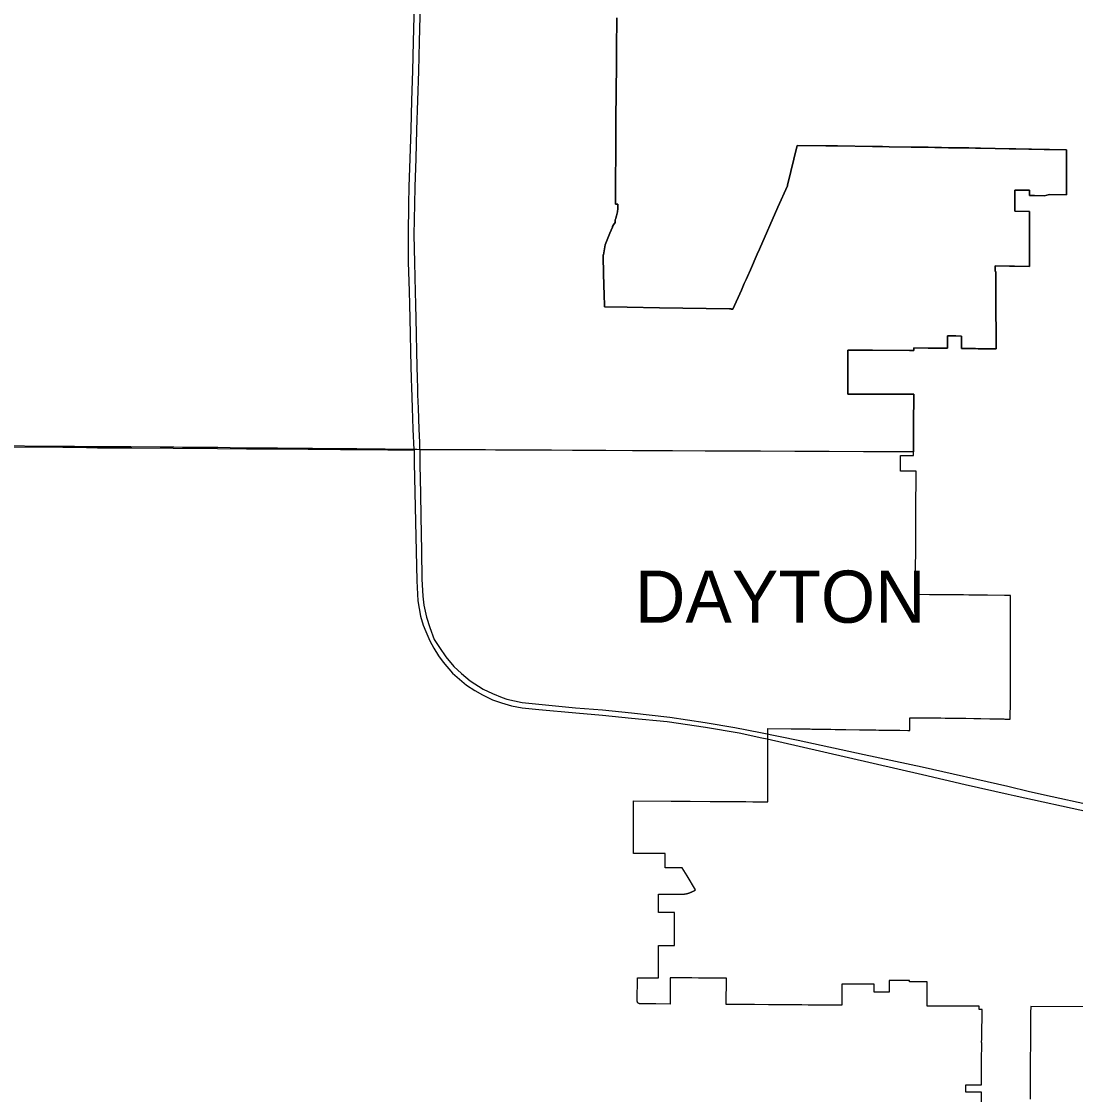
# Model space of a CAD drawing. Extents: x 0 to 34, y 0 to 22.
# Drawn here: x 4.8006 to 4.9631, y 15.001 to 15.1664 of the extents above; entities that cross this region are included whole.
import ezdxf

# ---------------------------------------------------------------- set-up
doc = ezdxf.new("R2010")
doc.units = 0
for name, color, linetype in [('GM_X_Corporation', 7, 'Continuous'), ('GM_X_Corporation_Text', 7, 'Continuous'), ('GM_X_State_Route', 7, 'Continuous'), ('GM_X_US_Route', 7, 'Continuous')]:
    doc.layers.add(name, color=color, linetype=linetype)

msp = doc.modelspace()

# ---------------------------------------------------------------- linework, layer by layer
at = {"layer": 'GM_X_Corporation'}
for points in [[(4.89236, 15.16696), (4.89235, 15.16538), (4.89234, 15.16383), (4.89233, 15.16245), (4.89231, 15.15985), (4.89224, 15.15131), (4.89223, 15.14958), (4.89222, 15.14797), (4.89221, 15.14771), (4.8922, 15.14658), (4.89216, 15.14146), (4.89214, 15.13825), (4.89253, 15.13825), (4.89253, 15.13812), (4.89254, 15.13802), (4.89253, 15.13791), (4.89253, 15.13781), (4.89253, 15.13771), (4.89252, 15.13761), (4.89251, 15.13751), (4.89251, 15.13741), (4.89249, 15.13731), (4.89249, 15.13724), (4.89248, 15.13721), (4.89247, 15.13711), (4.89245, 15.13701), (4.89243, 15.13691), (4.89241, 15.13681), (4.89239, 15.13671), (4.89237, 15.13662), (4.89234, 15.13652), (4.89232, 15.13642), (4.89229, 15.13634), (4.89229, 15.13632), (4.89226, 15.13623), (4.89223, 15.13613), (4.89219, 15.13604), (4.89216, 15.13594), (4.89212, 15.13585), (4.89212, 15.13544), (4.89187, 15.13507), (4.89172, 15.13483), (4.89168, 15.13474), (4.89129, 15.13379), (4.89065, 15.13224), (4.89055, 15.13201), (4.89033, 15.13047), (4.89026, 15.13047), (4.89026, 15.13027), (4.89027, 15.12998), (4.89038, 15.12557), (4.89041, 15.12449), (4.89045, 15.12243), (4.89395, 15.12237), (4.89893, 15.12229), (4.90974, 15.12211), (4.90989, 15.12211), (4.90991, 15.12211), (4.90993, 15.12211), (4.90993, 15.12211), (4.90994, 15.12211), (4.90996, 15.12211), (4.90997, 15.12211), (4.90998, 15.12211), (4.91, 15.12211), (4.91001, 15.1221), (4.91028, 15.1221), (4.91028, 15.1221), (4.91157, 15.125), (4.91201, 15.12601), (4.9123, 15.12667), (4.9125, 15.12711), (4.91296, 15.12815), (4.91401, 15.13053), (4.91437, 15.13134), (4.91721, 15.13778), (4.91867, 15.14107), (4.9187, 15.14119), (4.9202, 15.14732), (4.92462, 15.14726), (4.92543, 15.14724), (4.92638, 15.14723), (4.93179, 15.14716), (4.93336, 15.14713), (4.93436, 15.14712), (4.93776, 15.14707), (4.93816, 15.14707), (4.93932, 15.14705), (4.94037, 15.14703), (4.94141, 15.14701), (4.94235, 15.147), (4.94245, 15.14699), (4.9435, 15.14697), (4.94454, 15.14696), (4.94472, 15.14695), (4.94558, 15.14694), (4.94663, 15.14692), (4.94767, 15.1469), (4.94807, 15.14689), (4.94847, 15.14689), (4.95073, 15.14685), (4.95288, 15.14681), (4.95298, 15.14681), (4.95322, 15.1468), (4.95337, 15.1468), (4.95378, 15.14679), (4.95388, 15.14679), (4.95589, 15.14676), (4.95603, 15.14675), (4.95634, 15.14675), (4.95828, 15.14671), (4.95869, 15.14671), (4.95908, 15.1467), (4.9617, 15.14665), (4.9617, 15.14566), (4.9617, 15.14467), (4.9617, 15.14367), (4.96171, 15.14348), (4.96171, 15.14268), (4.96171, 15.14169), (4.96171, 15.14088), (4.96171, 15.14069), (4.96171, 15.14019), (4.96171, 15.14002), (4.96171, 15.1397), (4.9591, 15.13975), (4.9587, 15.13965), (4.9583, 15.13956), (4.95676, 15.13959), (4.95603, 15.1396), (4.95603, 15.1404), (4.9556, 15.14041), (4.95376, 15.14044), (4.95376, 15.13964), (4.95376, 15.13885), (4.95375, 15.13846), (4.95375, 15.13804), (4.95375, 15.13716), (4.95603, 15.13712), (4.95603, 15.13606), (4.95603, 15.135), (4.95603, 15.13394), (4.95603, 15.13288), (4.95603, 15.13182), (4.95603, 15.13076), (4.95603, 15.13012), (4.95603, 15.1297), (4.95603, 15.12917), (4.95603, 15.12864), (4.95372, 15.12868), (4.95334, 15.12869), (4.95292, 15.1287), (4.9507, 15.12874), (4.9507, 15.12799), (4.9507, 15.12786), (4.95082, 15.12786), (4.95082, 15.12705), (4.95083, 15.12625), (4.95083, 15.12561), (4.95083, 15.12497), (4.95083, 15.12432), (4.95083, 15.12368), (4.95084, 15.12304), (4.95084, 15.12295), (4.95084, 15.1224), (4.95084, 15.12175), (4.95084, 15.12111), (4.95084, 15.12047), (4.95085, 15.11983), (4.95085, 15.11918), (4.95085, 15.11854), (4.95085, 15.1179), (4.95085, 15.11726), (4.95086, 15.11661), (4.95086, 15.11597), (4.95073, 15.11597), (4.9506, 15.11597), (4.94849, 15.11595), (4.94808, 15.11598), (4.94807, 15.11598), (4.94769, 15.116), (4.94553, 15.11602), (4.94553, 15.11665), (4.94553, 15.11729), (4.94553, 15.11793), (4.94463, 15.11794), (4.94338, 15.11794), (4.94338, 15.11605), (4.94297, 15.11605), (4.94258, 15.11605), (4.9404, 15.11608), (4.93817, 15.1161), (4.93817, 15.11571), (4.93797, 15.11571), (4.93777, 15.11571), (4.93776, 15.11571), (4.93752, 15.11571), (4.9318, 15.11573), (4.92801, 15.11574), (4.92799, 15.10899), (4.93751, 15.10896), (4.93775, 15.10896), (4.93816, 15.10896), (4.93816, 15.10885), (4.93815, 15.1082), (4.93815, 15.10756), (4.93815, 15.10691), (4.93814, 15.10627), (4.93814, 15.10563), (4.93814, 15.10498), (4.93814, 15.10437), (4.93813, 15.10376), (4.93813, 15.10316), (4.93812, 15.101), (4.93812, 15.10008), (4.93776, 15.10008), (4.93771, 15.10008), (4.93614, 15.10007), (4.93573, 15.10007), (4.93061, 15.10009), (4.93043, 15.10009), (4.92512, 15.10012), (4.91981, 15.10014), (4.91452, 15.10017), (4.91131, 15.10018), (4.91106, 15.10019), (4.90609, 15.10021), (4.906, 15.10021), (4.90096, 15.10023), (4.9009, 15.10023), (4.89568, 15.10026), (4.89564, 15.10026), (4.89476, 15.10026), (4.89066, 15.10028), (4.89063, 15.10028), (4.8906, 15.10028), (4.89041, 15.10028), (4.88841, 15.10029), (4.88709, 15.1003), (4.88554, 15.1003), (4.88551, 15.1003), (4.8823, 15.10032), (4.8819, 15.10032), (4.87972, 15.10033), (4.8779, 15.10034), (4.87453, 15.10036), (4.87421, 15.10036), (4.87412, 15.10036), (4.87365, 15.10036), (4.87212, 15.10037), (4.87057, 15.10037), (4.86853, 15.10038), (4.86199, 15.10041), (4.86153, 15.10042), (4.86101, 15.10042), (4.85229, 15.10054), (4.85163, 15.10055), (4.8497, 15.10057), (4.84959, 15.10057), (4.84544, 15.10061), (4.84528, 15.10061), (4.84487, 15.10061), (4.84005, 15.10063), (4.83602, 15.10065), (4.83525, 15.10067), (4.83522, 15.10067), (4.83274, 15.10071), (4.83082, 15.10073), (4.83075, 15.10073), (4.83074, 15.10073), (4.83021, 15.10073), (4.82725, 15.10073), (4.82539, 15.10076), (4.82403, 15.10078), (4.82195, 15.1008), (4.81743, 15.10084), (4.81499, 15.10085), (4.81213, 15.10085), (4.81027, 15.10087), (4.80874, 15.10088), (4.8056, 15.1009), (4.80523, 15.1009), (4.79683, 15.10101)], [(4.94863, 14.99906), (4.9486, 15.00138), (4.94618, 15.00137), (4.94619, 15.00249), (4.9486, 15.0025), (4.94861, 15.00363), (4.94862, 15.00475), (4.94863, 15.00588), (4.94863, 15.007), (4.94864, 15.00813), (4.94864, 15.00895), (4.94863, 15.00909), (4.94865, 15.00955), (4.94867, 15.01056), (4.94871, 15.01332), (4.94871, 15.01365), (4.94872, 15.01413), (4.94825, 15.01413), (4.94825, 15.01461), (4.94649, 15.01461), (4.94481, 15.01461), (4.94287, 15.01462), (4.94264, 15.01462), (4.94135, 15.01462), (4.94024, 15.01462), (4.94025, 15.0184), (4.93751, 15.0184), (4.93751, 15.01859), (4.93519, 15.0186), (4.93439, 15.0186), (4.93439, 15.01848), (4.93439, 15.01681), (4.93205, 15.01681), (4.93205, 15.01802), (4.93203, 15.018), (4.93077, 15.01801), (4.92992, 15.01802), (4.92948, 15.01802), (4.92707, 15.01804), (4.92707, 15.01743), (4.92707, 15.01733), (4.92706, 15.01478), (4.9251, 15.01479), (4.92348, 15.0148), (4.92348, 15.0148), (4.92347, 15.0148), (4.92346, 15.0148), (4.92346, 15.0148), (4.92345, 15.0148), (4.92345, 15.0148), (4.92344, 15.0148), (4.92343, 15.0148), (4.92343, 15.0148), (4.92342, 15.0148), (4.92342, 15.0148), (4.92341, 15.0148), (4.9234, 15.0148), (4.92194, 15.01481), (4.92193, 15.01481), (4.92193, 15.01481), (4.92192, 15.01481), (4.92191, 15.01481), (4.92191, 15.01481), (4.9219, 15.01481), (4.9219, 15.01481), (4.9219, 15.01481), (4.92188, 15.01481), (4.92188, 15.01481), (4.92188, 15.01481), (4.92187, 15.01481), (4.92187, 15.01481), (4.92089, 15.01482), (4.92042, 15.01482), (4.91952, 15.01483), (4.9182, 15.01484), (4.91792, 15.01484), (4.91665, 15.01485), (4.91575, 15.01486), (4.91358, 15.01487), (4.91141, 15.01488), (4.90925, 15.0149), (4.9093, 15.01894), (4.90898, 15.01894), (4.90729, 15.01895), (4.90713, 15.01895), (4.90561, 15.01897), (4.90496, 15.01897), (4.90392, 15.01898), (4.90279, 15.01899), (4.90223, 15.01899), (4.90062, 15.019), (4.90057, 15.01496), (4.8984, 15.01497), (4.89808, 15.01498), (4.89593, 15.01499), (4.89592, 15.01499), (4.89592, 15.01499), (4.8959, 15.01499), (4.89589, 15.01499), (4.89588, 15.01499), (4.89588, 15.01499), (4.89586, 15.015), (4.89585, 15.015), (4.89585, 15.015), (4.89583, 15.015), (4.89583, 15.015), (4.89582, 15.01501), (4.89581, 15.01501), (4.89579, 15.01502), (4.89579, 15.01502), (4.89578, 15.01502), (4.89577, 15.01503), (4.89576, 15.01503), (4.89576, 15.01503), (4.89574, 15.01504), (4.89573, 15.01504), (4.89572, 15.01505), (4.89571, 15.01506), (4.89571, 15.01506), (4.8957, 15.01507), (4.89568, 15.01508), (4.89568, 15.01508), (4.89567, 15.01509), (4.89566, 15.01509), (4.89566, 15.0151), (4.89565, 15.0151), (4.89564, 15.01511), (4.89563, 15.01512), (4.89563, 15.01513), (4.89562, 15.01513), (4.89561, 15.01515), (4.89561, 15.01515), (4.89561, 15.01516), (4.8956, 15.01517), (4.89559, 15.01517), (4.89559, 15.01518), (4.89558, 15.01519), (4.89558, 15.0152), (4.89558, 15.0152), (4.89557, 15.01522), (4.89556, 15.01523), (4.89556, 15.01524), (4.89556, 15.01524), (4.89555, 15.01526), (4.89555, 15.01527), (4.89555, 15.01528), (4.89555, 15.01528), (4.89554, 15.0153), (4.89554, 15.01531), (4.89554, 15.01532), (4.89554, 15.01532), (4.89553, 15.01534), (4.89553, 15.01535), (4.89553, 15.01537), (4.89553, 15.01537), (4.89553, 15.01538), (4.89553, 15.01539), (4.89554, 15.01902), (4.89845, 15.01902), (4.89882, 15.01902), (4.89881, 15.02146), (4.89881, 15.02157), (4.89881, 15.02231), (4.89881, 15.02367), (4.89881, 15.02387), (4.89881, 15.024), (4.89895, 15.024), (4.90125, 15.024), (4.90125, 15.02405), (4.90125, 15.0241), (4.90125, 15.02415), (4.90125, 15.0242), (4.90125, 15.02569), (4.90124, 15.02738), (4.90124, 15.02907), (4.89881, 15.02906), (4.89881, 15.0311), (4.89881, 15.0319), (4.89985, 15.0319), (4.90202, 15.0319), (4.90237, 15.0319), (4.90243, 15.0319), (4.9025, 15.0319), (4.90256, 15.0319), (4.90262, 15.03191), (4.90268, 15.03191), (4.90275, 15.03192), (4.90281, 15.03192), (4.90287, 15.03193), (4.90293, 15.03194), (4.903, 15.03195), (4.90306, 15.03196), (4.90312, 15.03197), (4.90318, 15.03199), (4.90324, 15.032), (4.90331, 15.03202), (4.90337, 15.03204), (4.90343, 15.03205), (4.90349, 15.03207), (4.90355, 15.03209), (4.90361, 15.03211), (4.90367, 15.03213), (4.90372, 15.03216), (4.90378, 15.03218), (4.90384, 15.03221), (4.9039, 15.03223), (4.90396, 15.03226), (4.90401, 15.03229), (4.90407, 15.03232), (4.90412, 15.03235), (4.90418, 15.03238), (4.90426, 15.03243), (4.90451, 15.03258), (4.9032, 15.03473), (4.90245, 15.03596), (4.90202, 15.03597), (4.90079, 15.03597), (4.89985, 15.03597), (4.8998, 15.03597), (4.8998, 15.03814), (4.89494, 15.03816), (4.89495, 15.04629), (4.90073, 15.04624), (4.90366, 15.04622), (4.90674, 15.0462), (4.90941, 15.04618), (4.91118, 15.04616), (4.91141, 15.04616), (4.91225, 15.04616), (4.91336, 15.04615), (4.91402, 15.04614), (4.91567, 15.04613), (4.91567, 15.04699), (4.91568, 15.05479), (4.91568, 15.05745), (4.91927, 15.0574), (4.92003, 15.05739), (4.92007, 15.05739), (4.92218, 15.05736), (4.92244, 15.05735), (4.92454, 15.05732), (4.92535, 15.05731), (4.92606, 15.0573), (4.92745, 15.05728), (4.92771, 15.05728), (4.92981, 15.05725), (4.93061, 15.05724), (4.93232, 15.05721), (4.93278, 15.0572), (4.93304, 15.0572), (4.93521, 15.05717), (4.93601, 15.05716), (4.93727, 15.05714), (4.93757, 15.05713), (4.93758, 15.05794), (4.93758, 15.058), (4.93758, 15.05858), (4.93758, 15.05895), (4.93758, 15.05908), (4.93787, 15.05908), (4.93949, 15.05907), (4.94028, 15.05907), (4.94193, 15.05906), (4.94232, 15.05906), (4.94302, 15.05905), (4.9442, 15.05905), (4.94538, 15.05904), (4.94579, 15.05904), (4.9462, 15.05903), (4.94742, 15.059), (4.94849, 15.05898), (4.94988, 15.05895), (4.95031, 15.05894), (4.95203, 15.0589), (4.95221, 15.05889), (4.95301, 15.05888), (4.95301, 15.0589), (4.95306, 15.06166), (4.95306, 15.06214), (4.95307, 15.06238), (4.95307, 15.0627), (4.95308, 15.06738), (4.95308, 15.06804), (4.9531, 15.07796), (4.95214, 15.07796), (4.94952, 15.07798), (4.94927, 15.07799), (4.94665, 15.07801), (4.94585, 15.07802), (4.94473, 15.07802), (4.94374, 15.07803), (4.94348, 15.07803), (4.94138, 15.07805), (4.94057, 15.07806), (4.93843, 15.07808), (4.93843, 15.07872), (4.93843, 15.07936), (4.93844, 15.08), (4.93844, 15.08064), (4.93844, 15.08128), (4.93845, 15.08192), (4.93845, 15.08256), (4.93845, 15.0832), (4.93846, 15.08384), (4.93846, 15.08448), (4.93846, 15.08512), (4.93847, 15.08576), (4.93847, 15.0864), (4.93848, 15.08704), (4.93848, 15.08768), (4.93848, 15.08832), (4.93849, 15.08896), (4.93849, 15.0896), (4.93849, 15.0904), (4.93849, 15.09105), (4.9385, 15.09169), (4.9385, 15.09234), (4.9385, 15.09298), (4.9385, 15.09363), (4.93851, 15.09427), (4.93851, 15.09492), (4.93851, 15.09556), (4.93851, 15.09621), (4.93852, 15.09685), (4.93852, 15.09711), (4.93806, 15.09711), (4.93771, 15.09711), (4.93742, 15.09711), (4.93677, 15.09712), (4.93612, 15.09712), (4.93613, 15.09944), (4.93613, 15.09953), (4.93811, 15.09952), (4.93812, 15.10008), (4.93812, 15.101), (4.93813, 15.10316), (4.93813, 15.10376), (4.93814, 15.10437), (4.93814, 15.10498), (4.93814, 15.10563), (4.93814, 15.10627), (4.93815, 15.10691), (4.93815, 15.10756), (4.93815, 15.1082), (4.93816, 15.10885), (4.93816, 15.10896), (4.93775, 15.10896), (4.93751, 15.10896), (4.92799, 15.10899), (4.92801, 15.11574), (4.9318, 15.11573), (4.93752, 15.11571), (4.93776, 15.11571), (4.93817, 15.11571), (4.93817, 15.1161), (4.9404, 15.11608), (4.94258, 15.11605), (4.94297, 15.11605), (4.94338, 15.11605), (4.94338, 15.11794), (4.94463, 15.11794), (4.94553, 15.11793), (4.94553, 15.11729), (4.94553, 15.11665), (4.94553, 15.11602), (4.94769, 15.116), (4.94807, 15.11598), (4.94849, 15.11595), (4.9506, 15.11597), (4.95073, 15.11597), (4.95086, 15.11597), (4.95086, 15.11661), (4.95085, 15.11726), (4.95085, 15.1179), (4.95085, 15.11854), (4.95085, 15.11918), (4.95085, 15.11983), (4.95084, 15.12047), (4.95084, 15.12111), (4.95084, 15.12175), (4.95084, 15.1224), (4.95084, 15.12304), (4.95083, 15.12368), (4.95083, 15.12432), (4.95083, 15.12497), (4.95083, 15.12561), (4.95083, 15.12625), (4.95082, 15.12705), (4.95082, 15.12786), (4.9507, 15.12786), (4.9507, 15.12799), (4.9507, 15.12874), (4.95292, 15.1287), (4.95334, 15.12869), (4.95372, 15.12868), (4.95603, 15.12864), (4.95603, 15.12917), (4.95603, 15.1297), (4.95603, 15.13012), (4.95603, 15.13076), (4.95603, 15.13182), (4.95603, 15.13288), (4.95603, 15.13394), (4.95603, 15.135), (4.95603, 15.13606), (4.95603, 15.13712), (4.95375, 15.13716), (4.95375, 15.13804), (4.95375, 15.13846), (4.95375, 15.13856), (4.95376, 15.13885), (4.95376, 15.13964), (4.95376, 15.14044), (4.9556, 15.14041), (4.95603, 15.1404), (4.95603, 15.1396), (4.95676, 15.13959), (4.9583, 15.13956), (4.9587, 15.13965), (4.9591, 15.13975), (4.96171, 15.1397), (4.96171, 15.14002), (4.96171, 15.14019), (4.96171, 15.14069), (4.96171, 15.14088), (4.96171, 15.14169), (4.96171, 15.14268), (4.96171, 15.14348), (4.9617, 15.14367), (4.9617, 15.14467), (4.9617, 15.14566), (4.9617, 15.14665), (4.95908, 15.1467), (4.95869, 15.14671), (4.95828, 15.14671), (4.95634, 15.14675), (4.95603, 15.14675), (4.95589, 15.14676), (4.95388, 15.14679), (4.95378, 15.14679), (4.95337, 15.1468), (4.95322, 15.1468), (4.95298, 15.14681), (4.95288, 15.14681), (4.95073, 15.14685), (4.94847, 15.14689), (4.94807, 15.14689), (4.94767, 15.1469), (4.94663, 15.14692), (4.94558, 15.14694), (4.94472, 15.14695), (4.94454, 15.14696), (4.9435, 15.14697), (4.94245, 15.14699), (4.94235, 15.147), (4.94141, 15.14701), (4.94037, 15.14703), (4.93932, 15.14705), (4.93816, 15.14707), (4.93776, 15.14707), (4.93436, 15.14712), (4.93336, 15.14713), (4.93179, 15.14716), (4.92638, 15.14723), (4.92543, 15.14724), (4.92462, 15.14726), (4.9202, 15.14732), (4.9187, 15.14119), (4.91867, 15.14107), (4.91721, 15.13778), (4.91437, 15.13134), (4.91401, 15.13053), (4.91296, 15.12815), (4.9125, 15.12711), (4.9123, 15.12667), (4.91201, 15.12601), (4.91157, 15.125), (4.91028, 15.1221), (4.91028, 15.1221), (4.91001, 15.1221), (4.91, 15.12211), (4.90998, 15.12211), (4.90997, 15.12211), (4.90996, 15.12211), (4.90994, 15.12211), (4.90993, 15.12211), (4.90993, 15.12211), (4.90991, 15.12211), (4.90989, 15.12211), (4.90974, 15.12211), (4.89893, 15.12229), (4.89893, 15.12229), (4.89395, 15.12237), (4.89045, 15.12243), (4.89041, 15.12449), (4.89038, 15.12557), (4.89027, 15.12998), (4.89026, 15.13027), (4.89026, 15.13047), (4.89033, 15.13047), (4.89055, 15.13201), (4.89065, 15.13224), (4.89129, 15.13379), (4.89168, 15.13474), (4.89172, 15.13483), (4.89187, 15.13507), (4.89212, 15.13544), (4.89212, 15.13585), (4.89216, 15.13594), (4.89219, 15.13604), (4.89223, 15.13613), (4.89226, 15.13623), (4.89229, 15.13633), (4.89229, 15.13634), (4.89232, 15.13642), (4.89234, 15.13652), (4.89237, 15.13662), (4.89239, 15.13671), (4.89241, 15.13681), (4.89243, 15.13691), (4.89245, 15.13701), (4.89247, 15.13711), (4.89248, 15.13721), (4.89249, 15.13724), (4.89249, 15.13731), (4.89251, 15.13741), (4.89251, 15.13751), (4.89252, 15.13761), (4.89253, 15.13771), (4.89253, 15.13781), (4.89253, 15.13791), (4.89254, 15.13802), (4.89253, 15.13812), (4.89253, 15.13825), (4.89214, 15.13825), (4.89216, 15.14146), (4.8922, 15.14658), (4.89221, 15.14771), (4.89222, 15.14797), (4.89223, 15.14958), (4.89224, 15.15131), (4.89231, 15.15985), (4.89233, 15.16245), (4.89234, 15.16383), (4.89235, 15.16538), (4.89236, 15.16696)], [(4.97938, 15.01455), (4.95619, 15.01459), (4.95618, 15.01362), (4.95616, 15.01027), (4.95614, 15.00849), (4.95613, 15.00672), (4.95612, 15.00511), (4.95612, 15.00351), (4.95612, 15.00284), (4.95611, 15.0019), (4.95609, 15.00029)]]:
    msp.add_lwpolyline(points, dxfattribs=at)
at = {"layer": 'GM_X_State_Route'}
for points in [[(4.8611, 15.10039), (4.86098, 15.10358), (4.86084, 15.10686), (4.86074, 15.11006), (4.8607, 15.11127), (4.86061, 15.11547), (4.86054, 15.11833), (4.86043, 15.12282), (4.86037, 15.12483), (4.86026, 15.12932), (4.86022, 15.13357), (4.86029, 15.13826), (4.86036, 15.14093), (4.8605, 15.14531), (4.86063, 15.14975), (4.86077, 15.15425), (4.86089, 15.15879), (4.86102, 15.1633), (4.86113, 15.16726), (4.86126, 15.17174), (4.86139, 15.17618), (4.86152, 15.18052), (4.86163, 15.18438), (4.86174, 15.18753)], [(4.8617, 15.10886), (4.86166, 15.11004), (4.86163, 15.11126), (4.86153, 15.11545), (4.86147, 15.11831), (4.86136, 15.1228), (4.8613, 15.12474), (4.8612, 15.12929), (4.86114, 15.13355), (4.86121, 15.13824), (4.86128, 15.14091), (4.86142, 15.14529), (4.86155, 15.14973), (4.86169, 15.15423), (4.86181, 15.15877), (4.86194, 15.16328), (4.86206, 15.16724), (4.86218, 15.17172), (4.86232, 15.17616), (4.86243, 15.17989)], [(4.86199, 15.10039), (4.86198, 15.10157), (4.86191, 15.10356), (4.86177, 15.10684), (4.8617, 15.10886)]]:
    msp.add_lwpolyline(points, dxfattribs=at)
at = {"layer": 'GM_X_US_Route'}
for p, q in [((4.86006, 15.10038), (4.8611, 15.10039)), ((4.94611, 15.04881), (4.95272, 15.04729))]:
    msp.add_line(p, q, dxfattribs=at)
for points in [[(4.76749, 15.10119), (4.78265, 15.10104), (4.78584, 15.10095), (4.79161, 15.10092), (4.80692, 15.10078), (4.80787, 15.1008)], [(4.80787, 15.1008), (4.80882, 15.10081), (4.81227, 15.10072), (4.81755, 15.10069), (4.82396, 15.10067), (4.8308, 15.10059), (4.83524, 15.10054), (4.84012, 15.10053), (4.84478, 15.10048), (4.84551, 15.10049), (4.84977, 15.10046), (4.85068, 15.10045)], [(4.85068, 15.10045), (4.85159, 15.10044), (4.85704, 15.10038), (4.86006, 15.10038)], [(4.8611, 15.10039), (4.86113, 15.09838), (4.86151, 15.0802), (4.86166, 15.07711), (4.86211, 15.07477), (4.86249, 15.07335), (4.86289, 15.07239), (4.86351, 15.07097), (4.86416, 15.0698), (4.86487, 15.06863), (4.86561, 15.06766), (4.86704, 15.06596), (4.8692, 15.06414), (4.87049, 15.06329), (4.87164, 15.06261), (4.87317, 15.06186), (4.87456, 15.06138), (4.8761, 15.06092), (4.87776, 15.06062), (4.88033, 15.06036), (4.88603, 15.05984), (4.89018, 15.05949), (4.89462, 15.05904), (4.90014, 15.0585), (4.90606, 15.05762), (4.91121, 15.05677), (4.91475, 15.05602), (4.91557, 15.05583)], [(4.86199, 15.10039), (4.86201, 15.09806), (4.86208, 15.09366), (4.86215, 15.09009), (4.86225, 15.08481), (4.86232, 15.08045), (4.86245, 15.07784), (4.86261, 15.07647), (4.86302, 15.07462), (4.86352, 15.073), (4.86421, 15.07116), (4.86503, 15.0699), (4.86599, 15.06847), (4.86723, 15.06698), (4.86841, 15.06593), (4.86976, 15.06477), (4.87177, 15.06349), (4.87322, 15.06281), (4.8747, 15.06222), (4.87539, 15.06198), (4.87776, 15.06143), (4.88033, 15.06117), (4.88602, 15.06064), (4.89017, 15.06029), (4.89461, 15.05984)], [(4.89461, 15.05984), (4.90056, 15.05916), (4.90599, 15.05837), (4.91058, 15.05757), (4.91452, 15.05683), (4.92032, 15.05563), (4.93053, 15.05342), (4.93948, 15.05155), (4.95269, 15.04852)], [(4.91557, 15.05583), (4.9205, 15.0547), (4.93951, 15.05033), (4.94611, 15.04881)], [(4.95272, 15.04729), (4.95367, 15.04711), (4.96544, 15.04452), (4.97267, 15.04291), (4.97851, 15.0416), (4.98195, 15.04087), (4.98413, 15.04044), (4.98596, 15.04016), (4.98737, 15.04003), (4.98927, 15.04003), (4.99104, 15.04015), (4.99266, 15.04034), (4.99425, 15.04073), (4.99607, 15.04123), (4.99755, 15.04178), (4.99889, 15.04245), (5.00009, 15.04305), (5.00174, 15.04407), (5.00307, 15.04503), (5.00452, 15.0462), (5.00967, 15.05102), (5.01246, 15.05363), (5.0151, 15.05617)], [(4.95269, 15.04852), (4.95601, 15.04772), (4.9595, 15.04694), (4.96469, 15.04582)]]:
    msp.add_lwpolyline(points, dxfattribs=at)

# ---------------------------------------------------------------- texts
at = {"layer": 'GM_X_Corporation_Text'}
msp.add_text('DAYTON', height=0.008037, rotation=0, dxfattribs=at).set_placement((4.89518, 15.07374))

doc.saveas('drawing.dxf')
